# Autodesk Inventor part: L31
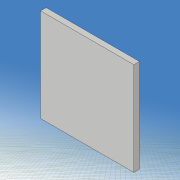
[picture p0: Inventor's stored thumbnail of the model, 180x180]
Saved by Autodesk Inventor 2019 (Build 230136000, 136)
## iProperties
Created: 2021-05
Part Number: L31
Material: 一般
Document SubType Name: Modeling
Designer: kikut
Density: 1 g/cm^3
Appearance: 既定
Mass: 0.00934248 g
Surface Area: 0.426451 cm^2
Volume: 0.00934248 cm^3
Author: kikut
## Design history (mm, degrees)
sketch "スケッチ1"
  geometry: L1 (80, 60)-(-80, 60); L2 (-80, 60)-(-80, -60); L3 (-80, -60)-(80, -60); L4 (80, -60)-(80, 60); L5 (80, 60)-(-80, -60); L6 (-80, 60)-(80, -60); 1 further point
  constraints: 12 end point, 2 midpoint, 2 parallel, 1 horizontal, 1 perpendicular
  dimensions: "d0" = 160 distance of L2.end L3.end; "d1" = 120 distance of L1.end L2.end
extrude "押し出し1" new body sketch "スケッチ1" stored distance "d2" = 0.6; taper "d3" = 0 deg
sketch "スケッチ2"
  geometry: L1 (-140, 0)-(140, 0) reference; L2 (0, -54)-(20, -30); L3 (0, 54)-(20, 30); L4 (0, -3)-(6.514, -3); L5 (6.514, -3)-(16, -6); L6 (16, -6)-(24, -3); L7 (24, -3)-(33.716, -3); L8 (0, 3)-(6.514, 3); L9 (6.514, 3)-(16, 6); L10 (16, 6)-(24, 3); L11 (24, 3)-(33.716, 3); L12 (0, -98)-(0, 98) reference; L13 (-100, -70)-(100, -70); L14 (100, -70)-(100, 70); L15 (100, 70)-(-100, 70); L16 (-100, 70)-(-100, -70); L17 (-100, -70)-(100, 70); L18 (100, -70)-(-100, 70); A1 r 60 centre (54.312, 28.5) between (0, 54) and (0, 3); A2 r 60 centre (54.312, -28.5) between (0, -3) and (0, -54); A3 r 18.111 centre (18, -12) between (20, -30) and (33.716, -3); A4 r 18.111 centre (18, 12) between (33.716, 3) and (20, 30); 1 further point
  constraints: 32 end point, 8 point on circle, 8 symmetric about line, 4 centre point, 3 horizontal, 2 collinear, 2 midpoint, 2 parallel, 1 perpendicular
  dimensions: "d5" = 60 radius of A1; "d6" = 6 distance of L8.start L4.start; "d7" = 108 distance of L3.start L2.start; "d8" = 0 horizontal distance of L3.start L8.start; "d9" = 60 distance of L3.end L2.end; "d10" = 0 horizontal distance of point (0, 0) L3.start; "d11" = 20 horizontal distance of L3.start L3.end; "d12" = 24 distance of A4.centre A3.centre; "d13" = 6 distance of L11.end L7.end; "d14" = 12 distance of L9.end L5.end; "d15" = 16 distance from line of L12 L5.end; "d16" = 24 distance from line of L6.end L12; "d17" = 200 distance of L14.end L15.end; "d18" = 140 distance of L15.end L13.start; "d30" = 18 distance from line of L12 A4.centre
extrude "押し出し2" cut sketch "スケッチ2" stored distance "d19" = 10; taper "d20" = 0 deg
sketch "スケッチ3"
  geometry: L1 (49.705, -17.97)-(33.948, -15.191); L2 (33.948, -15.191)-(34.295, -13.222); L3 (34.295, -13.222)-(50.052, -16); L4 (50.052, -16)-(49.705, -17.97); L5 (49.705, -17.97)-(34.295, -13.222); L6 (33.948, -15.191)-(50.052, -16); L7 (50.052, 16)-(34.295, 13.222); L8 (34.295, 13.222)-(33.948, 15.191); L9 (33.948, 15.191)-(49.705, 17.97); L10 (49.705, 17.97)-(50.052, 16); L11 (50.052, 16)-(33.948, 15.191); L12 (34.295, 13.222)-(49.705, 17.97); L13 (-112, 0)-(112, 0) reference; L14 (0, -84)-(0, 84) reference; 3 further points
  constraints: 24 end point, 4 midpoint, 4 parallel, 2 perpendicular, 2 symmetric about line
  dimensions: "d21" = 2 distance of L3.end L1.start; "d22" = 2 distance of L9.end L7.start; "d23" = 16 distance of L8.end L9.end; "d24" = 42 distance from line of L14 point (42, 15.596); "d26" = 10 deg angle of L7 L13; "d62" = 16 distance from line of L3.end L13
extrude "押し出し3" join sketch "スケッチ3" distance "d27" = 0.6; taper "d28" = 0 deg
fillet "フィレット1" dims "d31" = 2
fillet "フィレット2" dims "d32" = 1
sketch "スケッチ7"
  geometry: L1 (-20, 60)-(80, 60); L2 (80, 60)-(80, -60); L3 (80, -60)-(-20, -60); L4 (-20, -60)-(-20, 60); L5 (0, -82.207)-(0, 85.793) reference; L6 (-40, 0)-(100, 0) reference; L7 (20, -10)-(30, -10); L8 (30, -10)-(30, -20); L9 (30, -20)-(20, -20); L10 (20, -20)-(20, -10); 1 further point
  constraints: 16 end point, 4 parallel, 2 horizontal, 2 perpendicular, 1 other
  dimensions: "d80" = 120 distance of L3.end L1.start; "d81" = 20 distance between parallel lines of L5 L4; "d82" = 100 distance of L1.start L1.end; "d84" = 10 distance of L8.end L9.end; "d85" = 10 distance of L7.end L8.end; "d86" = 40 distance between parallel lines of L4 L10; "d93" = 40 distance between parallel lines of L3 L9
extrude "押し出し5" cut sketch "スケッチ7" stored distance "d87" = 10; taper "d88" = 0 deg
node "ソリッド1"
